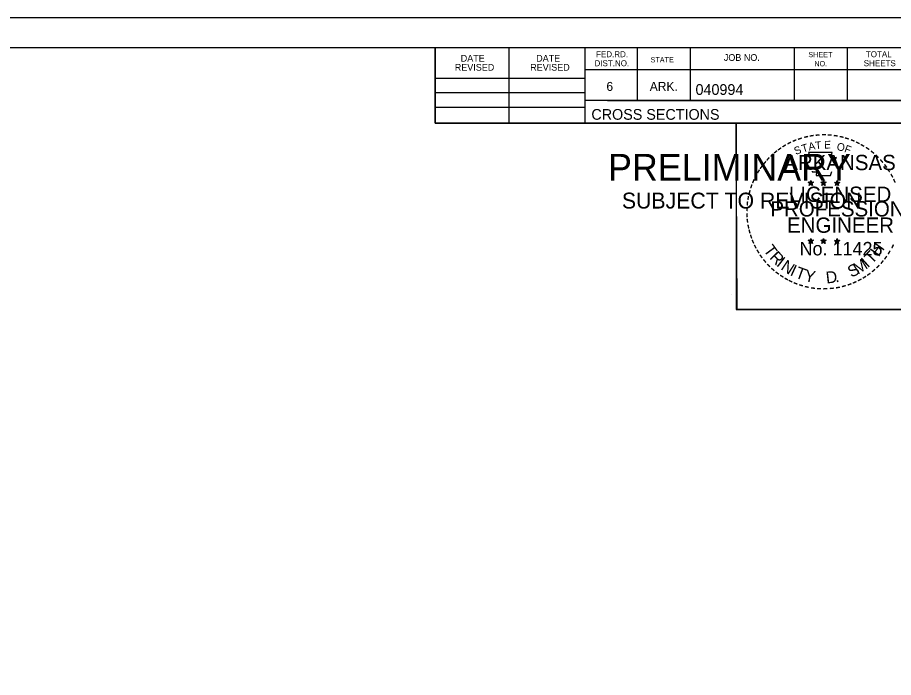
# Model space of a CAD drawing. Extents: x 1381471 to 1382703, y 370300 to 371487.
# Drawn here: x 1382177.6 to 1382292, y 370547.6 to 370633.8 of the extents above; entities that cross this region are included whole.
import ezdxf

# ---------------------------------------------------------------- set-up
doc = ezdxf.new("R2010")
doc.units = 0
doc.layers.add('Level 45', color=7, linetype='Continuous')

msp = doc.modelspace()

# ---------------------------------------------------------------- linework, layer by layer
at = {"layer": 'Level 45'}
for p, q in [((1381966.21, 370633.8), (1382299.55, 370633.8)), ((1381978.61, 370629.9), (1382294.79, 370629.9)), ((1382232.15, 370620.02), (1382232.15, 370629.9)), ((1382241.83, 370620.02), (1382241.83, 370629.9)), ((1382251.69, 370629.9), (1382251.69, 370620.02)), ((1382258.53, 370629.9), (1382258.53, 370622.96)), ((1382265.47, 370629.9), (1382265.47, 370622.96)), ((1382279.05, 370629.9), (1382279.05, 370622.96)), ((1382285.99, 370629.9), (1382285.99, 370622.96)), ((1382294.79, 370626.96), (1382251.69, 370626.96)), ((1382232.15, 370625.88), (1382251.69, 370625.88)), ((1382232.15, 370624.02), (1382251.69, 370624.02)), ((1382294.79, 370622.96), (1382251.69, 370622.96)), ((1382254.65, 370622.96), (1382294.79, 370622.96)), ((1382232.15, 370622.08), (1382251.69, 370622.08)), ((1382294.79, 370620.02), (1382232.15, 370620.02)), ((1382281.23, 370612.53), (1382281.19, 370612.28)), ((1382281.23, 370612.17), (1382281.23, 370612.53)), ((1382281.23, 370612.53), (1382281.28, 370612.28)), ((1382282.9, 370612.53), (1382282.86, 370612.28)), ((1382282.9, 370612.17), (1382282.9, 370612.53)), ((1382282.9, 370612.53), (1382282.95, 370612.28)), ((1382284.66, 370612.52), (1382284.62, 370612.27)), ((1382284.66, 370612.16), (1382284.66, 370612.52)), ((1382284.66, 370612.52), (1382284.71, 370612.27)), ((1382280.88, 370612.28), (1382281.23, 370612.17)), ((1382280.88, 370612.28), (1382281.13, 370612.23)), ((1382280.88, 370612.28), (1382281.12, 370612.16)), ((1382281.01, 370611.87), (1382281.23, 370612.17)), ((1382281.01, 370611.87), (1382281.14, 370612.12)), ((1382281.01, 370611.87), (1382281.23, 370612.09)), ((1382281.57, 370612.28), (1382281.23, 370612.17)), ((1382281.44, 370611.87), (1382281.23, 370612.17)), ((1382281.44, 370611.87), (1382281.23, 370612.09)), ((1382281.57, 370612.28), (1382281.29, 370612.23)), ((1382281.44, 370611.87), (1382281.3, 370612.16)), ((1382281.57, 370612.28), (1382281.37, 370612.18)), ((1382282.55, 370612.28), (1382282.9, 370612.17)), ((1382282.55, 370612.28), (1382282.8, 370612.23)), ((1382282.55, 370612.28), (1382282.79, 370612.16)), ((1382282.68, 370611.87), (1382282.9, 370612.17)), ((1382282.68, 370611.87), (1382282.81, 370612.12)), ((1382282.68, 370611.87), (1382282.9, 370612.09)), ((1382283.24, 370612.28), (1382282.9, 370612.17)), ((1382283.11, 370611.87), (1382282.9, 370612.17)), ((1382283.11, 370611.87), (1382282.9, 370612.09)), ((1382283.24, 370612.28), (1382282.96, 370612.23)), ((1382283.11, 370611.87), (1382282.97, 370612.16)), ((1382283.24, 370612.28), (1382283.04, 370612.18)), ((1382284.31, 370612.27), (1382284.66, 370612.16)), ((1382284.31, 370612.27), (1382284.57, 370612.22)), ((1382284.31, 370612.27), (1382284.55, 370612.15)), ((1382284.45, 370611.86), (1382284.66, 370612.16)), ((1382284.45, 370611.86), (1382284.57, 370612.1)), ((1382284.45, 370611.86), (1382284.66, 370612.08)), ((1382285.01, 370612.27), (1382284.66, 370612.16)), ((1382284.87, 370611.86), (1382284.66, 370612.16)), ((1382284.87, 370611.86), (1382284.66, 370612.07)), ((1382285.01, 370612.27), (1382284.72, 370612.22)), ((1382284.87, 370611.86), (1382284.74, 370612.15)), ((1382285.01, 370612.27), (1382284.8, 370612.17)), ((1382280.87, 370604.71), (1382281.22, 370604.6)), ((1382280.87, 370604.71), (1382281.13, 370604.66)), ((1382280.87, 370604.71), (1382281.11, 370604.58)), ((1382281.01, 370604.3), (1382281.22, 370604.6)), ((1382281.01, 370604.3), (1382281.13, 370604.54)), ((1382281.01, 370604.3), (1382281.22, 370604.52)), ((1382281.22, 370604.96), (1382281.18, 370604.71)), ((1382281.22, 370604.6), (1382281.22, 370604.96)), ((1382281.22, 370604.96), (1382281.27, 370604.71)), ((1382281.57, 370604.71), (1382281.22, 370604.6)), ((1382281.44, 370604.3), (1382281.22, 370604.6)), ((1382281.44, 370604.3), (1382281.22, 370604.51)), ((1382281.57, 370604.71), (1382281.28, 370604.66)), ((1382281.44, 370604.3), (1382281.3, 370604.59)), ((1382281.57, 370604.71), (1382281.37, 370604.6)), ((1382282.54, 370604.71), (1382282.89, 370604.6)), ((1382282.54, 370604.71), (1382282.8, 370604.66)), ((1382282.54, 370604.71), (1382282.78, 370604.58)), ((1382282.68, 370604.3), (1382282.89, 370604.6)), ((1382282.68, 370604.3), (1382282.8, 370604.54)), ((1382282.68, 370604.3), (1382282.89, 370604.52)), ((1382282.89, 370604.96), (1382282.85, 370604.71)), ((1382282.89, 370604.6), (1382282.89, 370604.96)), ((1382282.89, 370604.96), (1382282.94, 370604.71)), ((1382283.24, 370604.71), (1382282.89, 370604.6)), ((1382283.11, 370604.3), (1382282.89, 370604.6)), ((1382283.11, 370604.3), (1382282.89, 370604.51)), ((1382283.24, 370604.71), (1382282.95, 370604.66)), ((1382283.11, 370604.3), (1382282.97, 370604.59)), ((1382283.24, 370604.71), (1382283.04, 370604.6)), ((1382284.31, 370604.7), (1382284.66, 370604.59)), ((1382284.31, 370604.7), (1382284.56, 370604.65)), ((1382284.31, 370604.7), (1382284.55, 370604.57)), ((1382284.44, 370604.29), (1382284.66, 370604.59)), ((1382284.44, 370604.29), (1382284.57, 370604.53)), ((1382284.44, 370604.29), (1382284.66, 370604.51)), ((1382284.66, 370604.95), (1382284.62, 370604.7)), ((1382284.66, 370604.59), (1382284.66, 370604.95)), ((1382284.66, 370604.95), (1382284.71, 370604.7)), ((1382285.01, 370604.7), (1382284.66, 370604.59)), ((1382284.87, 370604.29), (1382284.66, 370604.59)), ((1382284.87, 370604.29), (1382284.66, 370604.5)), ((1382285.01, 370604.7), (1382284.72, 370604.65)), ((1382284.87, 370604.29), (1382284.74, 370604.58)), ((1382285.01, 370604.7), (1382284.8, 370604.59)), ((1382270.83, 370597.57), (1382270.83, 370597.57))]:
    msp.add_line(p, q, dxfattribs=at)
for points in [[(1381966.21, 370633.8), (1382299.55, 370633.8), (1382299.55, 370420.46), (1381966.21, 370420.46)], [(1382212.53, 370629.9), (1382232.15, 370629.9), (1382232.15, 370620.02), (1382248.27, 370620.02), (1382271.46, 370620.02), (1382271.46, 370595.69), (1382294.79, 370595.69), (1382294.79, 370424.44), (1381978.61, 370424.44), (1381978.61, 370629.9)], [(1382271.46, 370620.02), (1382294.67, 370620.02), (1382294.79, 370595.69), (1382271.59, 370595.69)]]:
    msp.add_lwpolyline(points, close=True, dxfattribs=at)
for points in [[(1382280.92, 370616.16), (1382281.19, 370615.33)], [(1382284.43, 370615.24), (1382284.57, 370615.52), (1382283.89, 370615.5), (1382284.04, 370616.16), (1382280.92, 370616.16)], [(1382281.41, 370613.73), (1382281.41, 370613.65), (1382281.97, 370613.63), (1382281.92, 370613.16), (1382283.79, 370613.16), (1382283.99, 370613.69)], [(1382281.23, 370612.53), (1382281.44, 370611.87), (1382280.88, 370612.28), (1382281.57, 370612.28), (1382281.01, 370611.87), (1382281.23, 370612.53)], [(1382282.9, 370612.53), (1382283.11, 370611.87), (1382282.55, 370612.28), (1382283.24, 370612.28), (1382282.68, 370611.87), (1382282.9, 370612.53)], [(1382284.66, 370612.52), (1382284.87, 370611.86), (1382284.31, 370612.27), (1382285.01, 370612.27), (1382284.45, 370611.86), (1382284.66, 370612.52)], [(1382281.22, 370604.96), (1382281.44, 370604.3), (1382280.87, 370604.71), (1382281.57, 370604.71), (1382281.01, 370604.3), (1382281.22, 370604.96)], [(1382282.89, 370604.96), (1382283.11, 370604.3), (1382282.54, 370604.71), (1382283.24, 370604.71), (1382282.68, 370604.3), (1382282.89, 370604.96)], [(1382284.66, 370604.95), (1382284.87, 370604.29), (1382284.31, 370604.7), (1382285.01, 370604.7), (1382284.44, 370604.29), (1382284.66, 370604.95)]]:
    msp.add_lwpolyline(points, dxfattribs=at)
for centre, radius in [((1382281.23, 370612.17), 0.172), ((1382281.23, 370612.17), 0.145), ((1382281.23, 370612.17), 0.116), ((1382281.23, 370612.17), 0.0991), ((1382281.23, 370612.17), 0.0747), ((1382281.23, 370612.17), 0.0495), ((1382281.23, 370612.17), 0.0296), ((1382282.9, 370612.17), 0.172), ((1382282.9, 370612.17), 0.145), ((1382282.9, 370612.17), 0.116), ((1382282.9, 370612.17), 0.0991), ((1382282.9, 370612.17), 0.0747), ((1382282.9, 370612.17), 0.0495), ((1382282.9, 370612.17), 0.0296), ((1382284.66, 370612.16), 0.172), ((1382284.66, 370612.16), 0.145), ((1382284.66, 370612.16), 0.116), ((1382284.66, 370612.16), 0.0991), ((1382284.66, 370612.16), 0.0747), ((1382284.66, 370612.16), 0.0495), ((1382284.66, 370612.16), 0.0296), ((1382281.22, 370604.59), 0.172), ((1382281.22, 370604.59), 0.145), ((1382281.22, 370604.59), 0.116), ((1382281.22, 370604.59), 0.0991), ((1382281.22, 370604.59), 0.0747), ((1382281.22, 370604.59), 0.0495), ((1382281.22, 370604.59), 0.0296), ((1382282.89, 370604.59), 0.172), ((1382282.89, 370604.59), 0.145), ((1382282.89, 370604.59), 0.116), ((1382282.89, 370604.59), 0.0991), ((1382282.89, 370604.59), 0.0747), ((1382282.89, 370604.59), 0.0495), ((1382282.89, 370604.59), 0.0296), ((1382284.66, 370604.58), 0.172), ((1382284.66, 370604.58), 0.145), ((1382284.66, 370604.58), 0.116), ((1382284.66, 370604.58), 0.0991), ((1382284.66, 370604.58), 0.0747), ((1382284.66, 370604.58), 0.0495), ((1382284.66, 370604.58), 0.0296)]:
    msp.add_circle(centre, radius, dxfattribs=at)

# ---------------------------------------------------------------- texts
for s, height, rotation, p in [('DATE', 0.879, 360, (1382235.49, 370628.04)), ('DATE', 0.879, 360, (1382245.35, 370628.04)), ('FED.RD.', 0.782, 360, (1382253.17, 370628.62)), ('STATE', 0.684, 360, (1382260.29, 370627.94)), ('JOB NO.', 0.879, 360, (1382269.87, 370628.14)), ('SHEET', 0.684, 360, (1382280.91, 370628.62)), ('TOTAL', 0.782, 360, (1382288.43, 370628.62)), ('REVISED', 0.879, 360, (1382234.71, 370626.86)), ('REVISED', 0.879, 360, (1382244.57, 370626.86)), ('DIST.NO.', 0.782, 360, (1382252.97, 370627.44)), ('NO.', 0.684, 360, (1382281.69, 370627.44)), ('SHEETS', 0.782, 360, (1382288.15, 370627.44)), ('6', 1.17, 360, (1382254.53, 370624.22)), ('ARK.', 1.172, 360, (1382260.19, 370624.22)), ('040994', 1.4, 360, (1382266.17, 370623.7)), ('CROSS SECTIONS', 1.4, 360, (1382252.56, 370620.45)), ('-', 1.6, 19.1761, (1382279.67, 370617.28)), ('-', 1.6, 13.6301, (1382280.42, 370617.53)), ('-', 1.6, 10.2193, (1382281.1, 370617.69)), ('-', 1.6, 5.8968, (1382281.82, 370617.8)), ('-', 1.6, 0.1862, (1382282.6, 370617.87)), ('-', 1.6, 357.743, (1382283.32, 370617.86)), ('-', 1.6, 352.1617, (1382284.06, 370617.8)), ('-', 1.6, 347.2049, (1382284.78, 370617.69)), ('-', 1.6, 342.3362, (1382285.42, 370617.53)), ('-', 1.6, 34.0636, (1382277.8, 370616.33)), ('-', 1.6, 28.7918, (1382278.4, 370616.7)), ('-', 1.6, 24.3072, (1382279.03, 370617.02)), ('S', 1, 21.594, (1382279.27, 370615.84)), ('T', 1, 16.4036, (1382280.19, 370616.17)), ('A', 1, 11.2132, (1382281.01, 370616.42)), ('T', 1, 6.0228, (1382281.86, 370616.58)), ('E', 1, 0.8323, (1382282.97, 370616.69)), ('O', 1, 350.4515, (1382284.57, 370616.48)), ('F', 1, 340.0707, (1382285.53, 370616.26)), ('-', 1.6, 337.8551, (1382286.15, 370617.31)), ('-', 1.6, 334.1211, (1382286.78, 370617.04)), ('-', 1.6, 329.6409, (1382287.36, 370616.75)), ('PRELIMINARY', 3.5, 360, (1382254.74, 370612.49)), ('-', 1.6, 42.9622, (1382276.32, 370615.14)), ('-', 1.6, 38.9507, (1382276.75, 370615.56)), ('-', 1.6, 36.2317, (1382277.23, 370615.93)), ('ARKANSAS', 2, 360, (1382277.77, 370613.87)), ('-', 1.6, 325.8627, (1382288.01, 370616.39)), ('-', 1.6, 320.5297, (1382288.62, 370615.97)), ('-', 1.6, 315.5786, (1382289.21, 370615.48)), ('-', 1.6, 50.6142, (1382275.47, 370614.17)), ('-', 1.6, 48.423, (1382275.87, 370614.66)), ('-', 1.6, 309.8797, (1382289.78, 370614.93)), ('-', 1.6, 306.6522, (1382290.31, 370614.33)), ('DWB', 0.01, 360, (1382255.49, 370614.34)), ('-', 1.6, 58.0706, (1382274.73, 370613.08)), ('-', 1.6, 54.2325, (1382275.05, 370613.61)), ('-', 1.4, 303.6753, (1382290.79, 370613.76)), ('-', 1.6, 67.7743, (1382274.16, 370611.86)), ('-', 1.6, 62.8713, (1382274.41, 370612.47)), ('-', 1.6, 299.6684, (1382291.11, 370613.15)), ('-', 1.6, 294.6628, (1382291.44, 370612.54)), ('-', 1.6, 75.461, (1382273.74, 370610.51)), ('-', 1.6, 72.3945, (1382273.94, 370611.23)), ('LICENSED', 2, 360, (1382278.37, 370609.72)), ('DWB', 0.01, 360, (1382281.21, 370612.16)), ('DWB', 0.01, 360, (1382282.88, 370612.16)), ('DWB', 0.01, 360, (1382284.65, 370612.15)), ('SUBJECT TO REVISION', 2.0751, 360, (1382256.55, 370608.86)), ('-', 1.6, 81.2013, (1382273.61, 370609.8)), ('-', 1.6, 89.0622, (1382273.51, 370608.41)), ('-', 1.6, 85.1863, (1382273.53, 370609.11)), ('PROFESSIONAL', 2, 360, (1382275.95, 370607.82)), ('-', 1.6, 94.1959, (1382273.54, 370607.68)), ('-', 1.6, 98.9479, (1382273.61, 370607.01)), ('-', 1.6, 101.7149, (1382273.75, 370606.28)), ('ENGINEER', 2, 360, (1382278.13, 370605.69)), ('-', 1.6, 105.4578, (1382273.91, 370605.69)), ('-', 1.6, 109.0874, (1382274.13, 370605.06)), ('-', 1.6, 114.0643, (1382274.38, 370604.46)), ('No. 11425', 1.757, 360, (1382279.76, 370602.74)), ('DWB', 0.01, 360, (1382281.21, 370604.59)), ('DWB', 0.01, 360, (1382282.88, 370604.59)), ('DWB', 0.01, 360, (1382284.65, 370604.58)), ('H', 1.54, 54.6088, (1382290.1, 370602.47)), ('-', 1.6, 115.7289, (1382274.68, 370603.84)), ('-', 1.6, 120.4471, (1382275.04, 370603.26)), ('T', 1.54, 306.0406, (1382274.98, 370603.43)), ('R', 1.54, 314.005, (1382275.75, 370602.39)), ('T', 1.54, 46.6444, (1382289.21, 370601.53)), ('-', 1.6, 239.0712, (1382291.12, 370603.75)), ('-', 1.6, 244.6197, (1382291.52, 370604.5)), ('-', 1.6, 125.8934, (1382275.44, 370602.69)), ('-', 1.6, 130.7181, (1382275.91, 370602.14)), ('I', 1.54, 321.9694, (1382276.65, 370601.45)), ('N', 1.54, 326.5002, (1382277.21, 370600.98)), ('M', 1.54, 32.6563, (1382287.37, 370600.2)), ('I', 1.54, 42.1136, (1382288.65, 370601.05)), ('-', 1.6, 231.2538, (1382290.29, 370602.53)), ('-', 1.6, 233.8452, (1382290.72, 370603.09)), ('-', 1.6, 134.2238, (1382276.42, 370601.6)), ('-', 1.6, 138.9338, (1382276.95, 370601.13)), ('I', 1.54, 335.3603, (1382278.42, 370600.2)), ('T', 1.54, 339.8912, (1382279.08, 370599.87)), ('Y', 1.54, 347.8556, (1382280.3, 370599.42)), ('S', 1.54, 26.9312, (1382286.53, 370599.8)), ('-', 1.6, 221.0851, (1382289.29, 370601.46)), ('-', 1.6, 225.7653, (1382289.81, 370601.96)), ('-', 1.6, 144.6463, (1382277.5, 370600.73)), ('-', 1.6, 148.0898, (1382278.07, 370600.36)), ('-', 1.6, 151.5704, (1382278.64, 370600.03)), ('D', 1.54, 6.3969, (1382283.28, 370599.06)), ('-', 1.6, 212.2491, (1382288.21, 370600.6)), ('-', 1.6, 215.7363, (1382288.74, 370600.98)), ('-', 1.6, 154.6002, (1382279.17, 370599.78)), ('-', 1.6, 158.5612, (1382279.79, 370599.53)), ('-', 1.6, 162.7983, (1382280.48, 370599.32)), ('-', 1.6, 167.5555, (1382281.19, 370599.15)), ('-', 1.6, 191.2858, (1382285, 370599.22)), ('.', 1.54, 13.7642, (1382284.48, 370599.19)), ('-', 1.6, 195.4743, (1382285.73, 370599.42)), ('-', 1.6, 200.7184, (1382286.41, 370599.66)), ('-', 1.6, 204.2516, (1382287.03, 370599.93)), ('-', 1.6, 207.3568, (1382287.65, 370600.25)), ('-', 1.6, 173.1155, (1382281.96, 370599.04)), ('-', 1.6, 176.5183, (1382282.71, 370598.99)), ('-', 1.6, 181.5918, (1382283.46, 370599.01)), ('-', 1.6, 185.8167, (1382284.27, 370599.09))]:
    msp.add_text(s, height=height, rotation=rotation, dxfattribs=at).set_placement(p)

doc.saveas('drawing.dxf')
